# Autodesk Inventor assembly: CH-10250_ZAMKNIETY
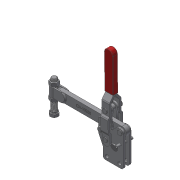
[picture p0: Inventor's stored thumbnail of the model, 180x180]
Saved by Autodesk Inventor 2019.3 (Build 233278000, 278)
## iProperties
Company: Î¢ÈíÖÐ¹ú
Created: 2012-09
Part Number: CH-10250_ZAMKNIETY
Material: Ogólny
Description: STEP AP203
Document SubType Name: Assembly
Designer: CADENGINEERING4
Sending System: SolidWorks 2010
Preprocessor: SwSTEP 2.0
Title: CH-10250.STEP
Author: Î¢ÈíÓÃ»§
Revision Number: ÈÎºÎ
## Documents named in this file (17)
- D:\Vault_2016\Projekty\NASZ KATALOG\CLAMPTEK\STRONA\Vertical toggle clamp\CH-10250\CH-10250_ZAMKNIETY.iam
- D:\Vault_2016\Projekty\NASZ KATALOG\CLAMPTEK\STEP FILES\Vertical toggle clamp\CH-10250\CH-10247-06.ipt
- D:\Vault_2016\Projekty\NASZ KATALOG\CLAMPTEK\STEP FILES\Vertical toggle clamp\CH-10250\CH-10247-08.ipt
- D:\Vault_2016\Projekty\NASZ KATALOG\CLAMPTEK\STEP FILES\Vertical toggle clamp\CH-10250\CH-SA-12300 NUT.ipt
- D:\Vault_2016\Projekty\NASZ KATALOG\CLAMPTEK\STEP FILES\Vertical toggle clamp\CH-10250\CH-10247-03 HANDLE.ipt
- D:\Vault_2016\Projekty\NASZ KATALOG\CLAMPTEK\STEP FILES\Vertical toggle clamp\CH-10250\CH-SA-12300 SPINDLE SUPPLIED.ipt
- D:\Vault_2016\Projekty\NASZ KATALOG\CLAMPTEK\STEP FILES\Vertical toggle clamp\CH-10250\CH-10250-02 SOLID BAR_Ä¬ÈÏ_°´¼Ó¹¤_.ipt
- D:\Vault_2016\Projekty\NASZ KATALOG\CLAMPTEK\STEP FILES\Vertical toggle clamp\CH-10250\CH-10247-11.ipt
- D:\Vault_2016\Projekty\NASZ KATALOG\CLAMPTEK\STEP FILES\Vertical toggle clamp\CH-10250\CH-10247-09.ipt
- D:\Vault_2016\Projekty\NASZ KATALOG\CLAMPTEK\STEP FILES\Vertical toggle clamp\CH-10250\M6 Nut.ipt
- D:\Vault_2016\Projekty\NASZ KATALOG\CLAMPTEK\STEP FILES\Vertical toggle clamp\CH-10250\CH-10247-05.ipt
- D:\Vault_2016\Projekty\NASZ KATALOG\CLAMPTEK\STEP FILES\Vertical toggle clamp\CH-10250\CH-10247-04 CONNECTING-PLATE.ipt
- D:\Vault_2016\Projekty\NASZ KATALOG\CLAMPTEK\STEP FILES\Vertical toggle clamp\CH-10250\CH-10247-07.ipt
- D:\Vault_2016\Projekty\NASZ KATALOG\CLAMPTEK\STEP FILES\Vertical toggle clamp\CH-10250\CH-10248-01 STRAIGHT BASE.ipt
- D:\Vault_2016\Projekty\NASZ KATALOG\CLAMPTEK\STEP FILES\Vertical toggle clamp\CH-10250\CH-10247-10.ipt
- D:\Vault_2016\Projekty\NASZ KATALOG\CLAMPTEK\STEP FILES\Vertical toggle clamp\CH-10250\3-8-16 LOCK NUT.ipt
- D:\Vault_2016\Projekty\NASZ KATALOG\CLAMPTEK\STEP FILES\Vertical toggle clamp\CH-10250\M6X25.ipt
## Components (21 placed, 21 different names)
1. CH-10247-06_1
2. CH-10247-08_2
3. CH-SA-12300 NUT_3
4. CH-10247-03 HANDLE_4
5. CH-SA-12300 SPINDLE SUPPLIED_5
6. CH-10250-02 SOLID BAR_Ä¬ÈÏ<°´¼Ó¹¤>_6
7. CH-10247-11_7
8. CH-10247-09_8
9. M6 Nut_9
10. CH-10247-05_10
11. CH-10247-11_11
12. CH-SA-12300 NUT_12
13. CH-10247-04 CONNECTING-PLATE_13
14. CH-10247-07_14
15. CH-10248-01 STRAIGHT BASE_15
16. CH-10247-08_16
17. CH-10247-10_17
18. 3-8-16 LOCK NUT_18
19. CH-10247-06_19
20. M6X25_20
21. 3-8-16 LOCK NUT_21
